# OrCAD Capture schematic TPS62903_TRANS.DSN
size E; title: TPS62903, 3-V to 17-V, High Efficiency and Low IQ; rev: 1.0; note: Datasheet: SLVSES3A                    EVM: SNVU745A; note: Synchronous Step Down Converter
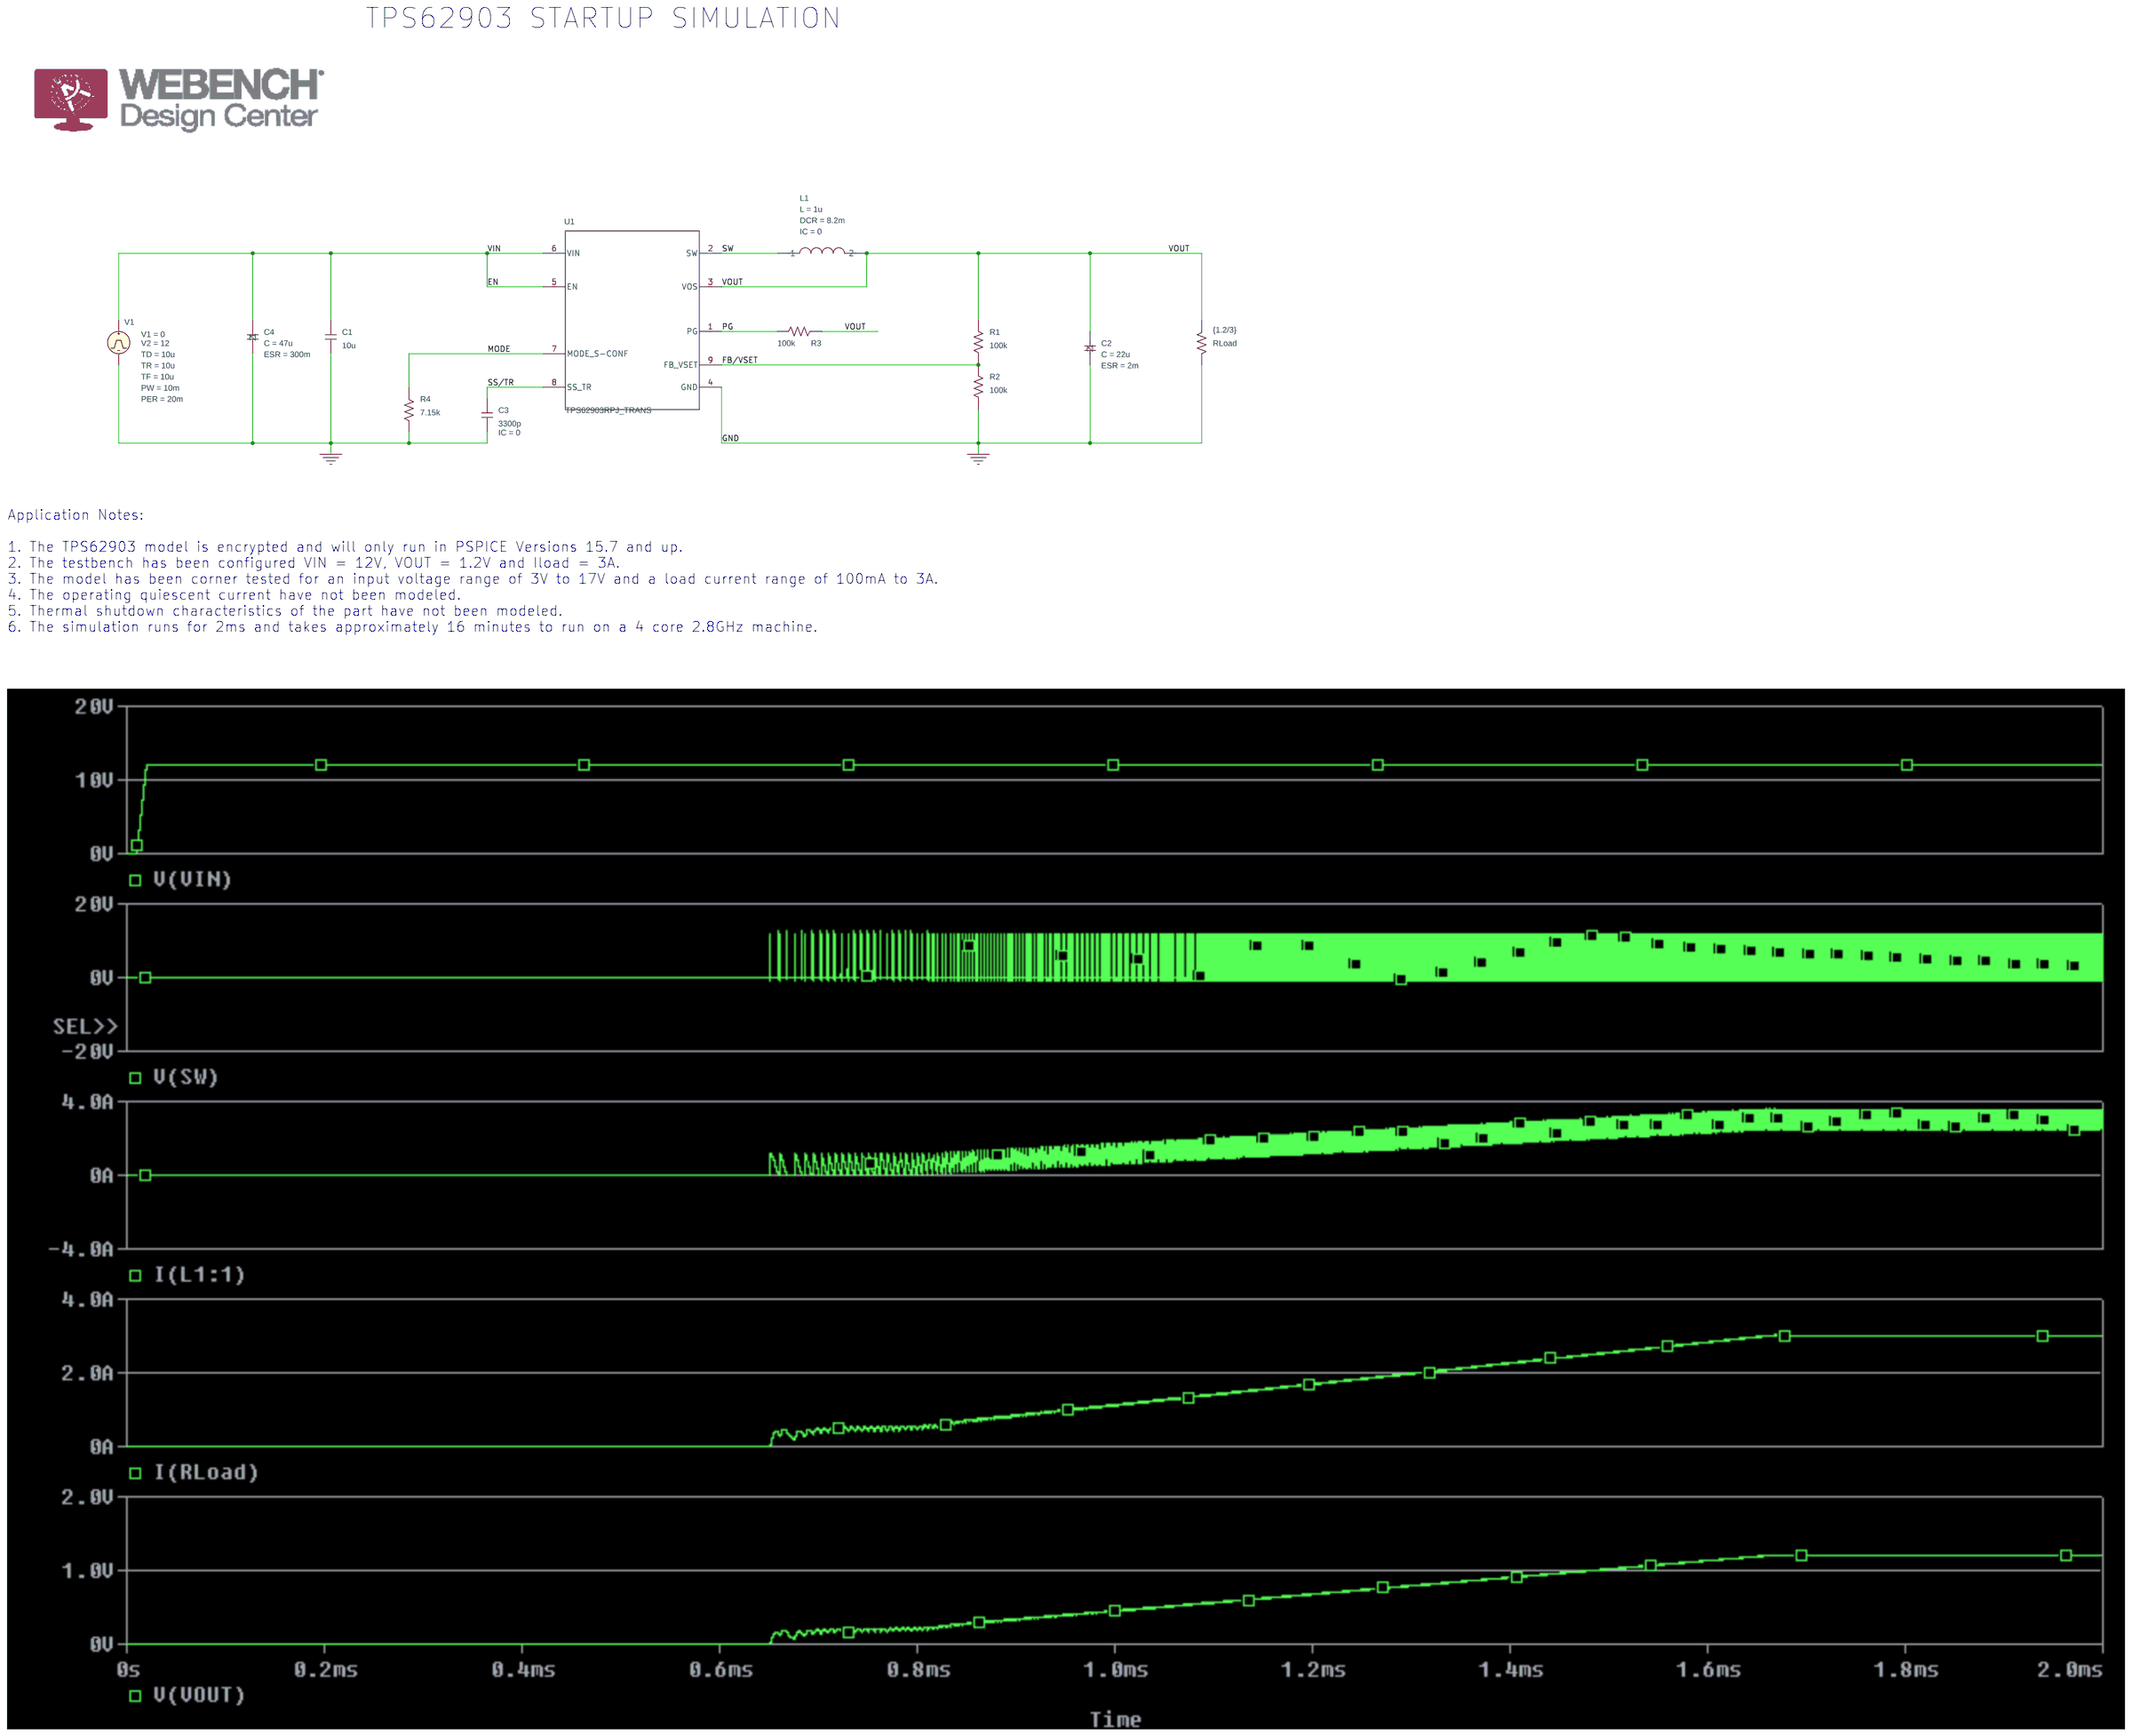
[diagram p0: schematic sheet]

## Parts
C1  10u  [RAD/CK05]
C2  CESR
C3  3300p  [RAD/CK05]
C4  CESR
L1  LDCR
R1  100k  [AX/RC05]
R2  100k  [AX/RC05]
R3  100k  [AX/RC05]
R4  7.15k  [AX/RC05]
RLoad  {1.2/3}  [AX/RC05]
U1  TPS62903RPJ_TRANS  [RPJ0009A]
V1  VPULSE

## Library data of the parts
C1 = C
C2 = CESR: C: 22u; ESR: 2m; IC: 0; PSpiceTemplate: X^@REFDES %1 %2 @MODEL PARAMS: ?C|C=@C||C=10U| ?ESR|ESR=@ESR||ESR=2M| ?IC|IC=@IC||IC=1N| ?X|X=@X||X=1|; X: 1
C3 = C: IC: 0
C4 = CESR_1: C: 47u; ESR: 300m; IC: 0; PSpiceTemplate: X^@REFDES %1 %2 @MODEL PARAMS: ?C|C=@C||C=10U| ?ESR|ESR=@ESR||ESR=2M| ?IC|IC=@IC||IC=1N| ?X|X=@X||X=1|; X: 1
L1 = LDCR: DCR: 8.2m; IC: 0; L: 1u
R1-R4 RLoad = R
U1 = TPS62903RPJ_TRANS
V1 = VPULSE: PER: 20m; PW: 10m; TD: 10u; TF: 10u; TR: 10u; V1: 0; V2: 12

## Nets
0: C1.2 C2.2 C3.2 C4.2 R2.1 R4.2 RLoad.2 U1.4(GND) V1.2(-)
EN: C1.1 C4.1 U1.5(EN) U1.6(VIN) V1.1(+)
FB/VSET: R1.1 R2.2 U1.9(FB_VSET)
MODE: R4.1 U1.7(MODE_S-CONF)
PG: R3.2 U1.1(PG)
SS/TR: C3.1 U1.8(SS_TR)
SW: L1.1 U1.2(SW)
VOUT: C2.1 L1.2 R1.2 R3.1 RLoad.1 U1.3(VOS)

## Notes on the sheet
- TPS62903 STARTUP SIMULATION
- Application Notes:
  1. The TPS62903 model is encrypted and will only run in PSPICE Versions 15.7 and up.
  2. The testbench has been configured VIN = 12V, VOUT = 1.2V and Iload = 3A.
  3. The model has been corner tested for an input voltage range of 3V to 17V and a load current range of 100mA to 3A.
  4. The operating quiescent current have not been modeled.
  5. Thermal shutdown characteristics of the part have not been modeled.
  6. The simulation runs for 2ms and takes approximately 16 minutes to run on a 4 core 2.8GHz machine.
